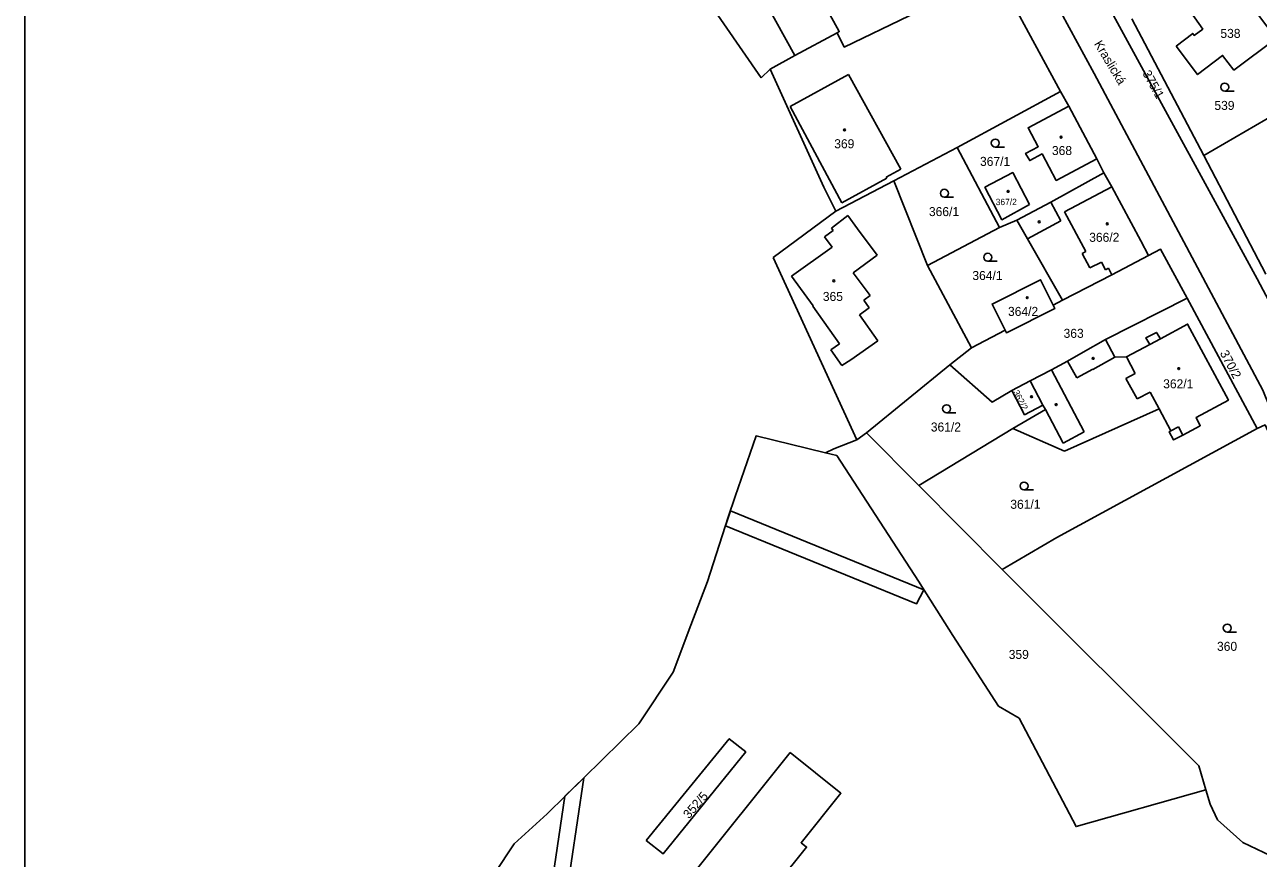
# Model space of a CAD drawing. Extents: x -869103 to -863415, y -1015889 to -1012477.
# Drawn here: x -867500 to -867267.3, y -1013218.1 to -1013060.8 of the extents above; entities that cross this region are included whole.
import ezdxf

# ---------------------------------------------------------------- set-up
doc = ezdxf.new("R2010")
doc.units = 0
for name, color, linetype in [('Hranice katastralního území', 7, 'Continuous'), ('Hranice parcel', 7, 'Continuous'), ('ML1000', 7, 'Continuous'), ('Parcelní čísla', 7, 'Continuous'), ('Pop  PČ popisy', 7, 'Continuous'), ('Vnitřní kresba', 7, 'Continuous'), ('Věcná břemena k části', 7, 'Continuous'), ('Značky budov', 7, 'Continuous'), ('Značky kultur', 7, 'Continuous')]:
    doc.layers.add(name, color=color, linetype=linetype)

msp = doc.modelspace()

# ---------------------------------------------------------------- linework, layer by layer
at = {"layer": 'Hranice katastralního území'}
for p, q in [((-867361.08, -1013070.83), (-867380.1, -1013043.27)), ((-867359.38, -1013069.2), (-867361.08, -1013070.83)), ((-867349.26, -1013091.48), (-867359.38, -1013069.2)), ((-867346.98, -1013096.01), (-867349.26, -1013091.48)), ((-867358.82, -1013104.69), (-867346.98, -1013096.01)), ((-867343.04, -1013139.1), (-867358.82, -1013104.69)), ((-867347.35, -1013140.84), (-867343.04, -1013139.1)), ((-867348.95, -1013141.56), (-867347.35, -1013140.84))]:
    msp.add_line(p, q, dxfattribs=at)
msp.add_lwpolyline([(-867412.61, -1013256.47), (-867414.85, -1013252.98), (-867416.96, -1013249.69), (-867421.06, -1013242.63), (-867420.77, -1013236.63), (-867419.53, -1013233.23), (-867415.2, -1013226.72), (-867407.64, -1013215.36), (-867401.46, -1013209.68), (-867384.12, -1013192.69), (-867377.65, -1013182.96), (-867374.36, -1013174.11), (-867371.17, -1013165.85), (-867367.29, -1013153.73), (-867365.95, -1013149.84), (-867362.01, -1013138.39), (-867348.95, -1013141.56)], dxfattribs=at)
at = {"layer": 'Hranice parcel'}
for p, q in [((-867361.08, -1013070.83), (-867380.1, -1013043.27)), ((-867304.61, -1013073.43), (-867315.9, -1013052.46)), ((-867298.26, -1013070), (-867307.69, -1013052.53)), ((-867291.15, -1013059.69), (-867277.56, -1013085.49)), ((-867354.69, -1013066.58), (-867346.74, -1013062.33)), ((-867354.69, -1013066.58), (-867359.38, -1013069.2)), ((-867359.38, -1013069.2), (-867361.08, -1013070.83)), ((-867349.26, -1013091.48), (-867359.38, -1013069.2)), ((-867304.61, -1013073.43), (-867324.1, -1013083.99)), ((-867303.02, -1013076.2), (-867304.61, -1013073.43)), ((-867297.75, -1013086.1), (-867303.02, -1013076.2)), ((-867277.56, -1013085.49), (-867261.75, -1013076.31)), ((-867324.1, -1013083.99), (-867336.02, -1013090.25)), ((-867316.12, -1013099.03), (-867324.1, -1013083.99)), ((-867296.4, -1013088.72), (-867297.75, -1013086.1)), ((-867277.56, -1013085.49), (-867265.83, -1013107.87)), ((-867346.98, -1013096.01), (-867349.26, -1013091.48)), ((-867336.02, -1013090.25), (-867346.98, -1013096.01)), ((-867336.02, -1013090.25), (-867329.69, -1013106.24)), ((-867358.82, -1013104.69), (-867346.98, -1013096.01)), ((-867312.83, -1013097.66), (-867316.12, -1013099.03)), ((-867316.12, -1013099.03), (-867329.69, -1013106.24)), ((-867343.04, -1013139.1), (-867358.82, -1013104.69)), ((-867329.69, -1013106.24), (-867321.39, -1013121.76)), ((-867260.77, -1013121.49), (-867267.49, -1013108.76)), ((-867296.12, -1013120.19), (-867280.67, -1013112.38)), ((-867267.48, -1013136.99), (-867280.67, -1013112.38)), ((-867304.19, -1013112.8), (-867306, -1013113.74)), ((-867315.03, -1013118.45), (-867321.39, -1013121.76)), ((-867321.39, -1013121.76), (-867325.46, -1013124.98)), ((-867325.46, -1013124.98), (-867341.22, -1013137.8)), ((-867313.78, -1013129.81), (-867310.31, -1013128.01)), ((-867310.31, -1013128.01), (-867307.91, -1013132.55)), ((-867341.22, -1013137.8), (-867343.04, -1013139.1)), ((-867331.35, -1013147.75), (-867341.22, -1013137.8)), ((-867313.57, -1013137), (-867331.35, -1013147.75)), ((-867303.82, -1013141.23), (-867313.57, -1013137)), ((-867347.35, -1013140.84), (-867343.04, -1013139.1)), ((-867348.95, -1013141.56), (-867347.35, -1013140.84)), ((-867315.6, -1013163.61), (-867331.35, -1013147.75))]:
    msp.add_line(p, q, dxfattribs=at)
for points in [[(-867267.49, -1013108.76), (-867293.45, -1013061.16), (-867304.41, -1013041.02)], [(-867346.74, -1013062.33), (-867346.32, -1013062.11), (-867353.77, -1013048.52), (-867362.18, -1013053.03), (-867354.69, -1013066.58)], [(-867315.9, -1013052.46), (-867320.88, -1013053.15), (-867345.39, -1013065.02), (-867346.74, -1013062.33)], [(-867282.8, -1013064.84), (-867278.72, -1013070.22), (-867274.01, -1013066.61), (-867271.88, -1013069.37), (-867263.9, -1013063.38), (-867272.32, -1013052.18), (-867276.15, -1013055.03), (-867276.98, -1013053.9), (-867281.08, -1013056.94), (-867277.77, -1013061.63), (-867279.35, -1013062.81), (-867279.64, -1013062.43), (-867282.8, -1013064.84)], [(-867264.14, -1013135.32), (-867266.41, -1013129.74), (-867298.26, -1013070)], [(-867297.75, -1013086.1), (-867305.39, -1013090.17), (-867308.06, -1013085.19), (-867310.38, -1013086.43), (-867311.19, -1013085.07), (-867308.79, -1013083.83), (-867310.71, -1013080.24), (-867303.02, -1013076.2)], [(-867310.42, -1013094.74), (-867315.64, -1013097.6), (-867318.86, -1013091.48), (-867313.59, -1013088.71), (-867310.42, -1013094.74)], [(-867296.4, -1013088.72), (-867306.4, -1013094.25), (-867312.83, -1013097.66)], [(-867287.99, -1013104.36), (-867289.46, -1013101.55), (-867294.9, -1013091.36), (-867296.4, -1013088.72)], [(-867304.19, -1013112.8), (-867310.8, -1013101.22), (-867312.83, -1013097.66)], [(-867287.99, -1013104.36), (-867294.9, -1013107.96), (-867304.19, -1013112.8)], [(-867280.67, -1013112.38), (-867285.73, -1013103.14), (-867287.99, -1013104.36)], [(-867315.03, -1013118.45), (-867317.51, -1013113.51), (-867308.35, -1013108.93), (-867306, -1013113.74)], [(-867306, -1013113.74), (-867305.69, -1013114.37), (-867314.79, -1013118.93), (-867315.03, -1013118.45)], [(-867296.12, -1013120.19), (-867294.35, -1013123.53), (-867292.17, -1013123.49), (-867287.75, -1013121.12), (-867288.52, -1013119.9), (-867286.51, -1013118.86), (-867285.74, -1013120.04), (-867280.61, -1013117.29), (-867272.92, -1013131.61), (-867279, -1013134.88), (-867278.22, -1013136.47), (-867281.53, -1013138.22), (-867283.26, -1013139.14), (-867284.09, -1013137.58), (-867283.78, -1013137.42), (-867286, -1013133.25), (-867303.82, -1013141.23)], [(-867310.31, -1013128.01), (-867306.27, -1013125.91), (-867303.27, -1013124.27), (-867300.34, -1013122.55), (-867300.31, -1013122.61), (-867296.12, -1013120.19)], [(-867325.46, -1013124.98), (-867317.46, -1013132), (-867313.78, -1013129.81)], [(-867307.91, -1013132.55), (-867311.36, -1013134.38), (-867313.78, -1013129.81)], [(-867313.57, -1013137), (-867307.45, -1013133.42), (-867307.91, -1013132.55)], [(-867267.48, -1013136.99), (-867305.28, -1013157.54), (-867315.6, -1013163.61)], [(-867243.12, -1013205.2), (-867247.84, -1013187.36), (-867252.77, -1013171.09), (-867262.16, -1013144.85), (-867265.99, -1013136.32), (-867267.48, -1013136.99)], [(-867412.61, -1013256.47), (-867414.85, -1013252.98), (-867416.96, -1013249.69), (-867421.06, -1013242.63), (-867420.77, -1013236.63), (-867419.53, -1013233.23), (-867415.2, -1013226.72), (-867407.64, -1013215.36), (-867401.46, -1013209.68), (-867384.12, -1013192.69), (-867377.65, -1013182.96), (-867374.36, -1013174.11), (-867371.17, -1013165.85), (-867367.29, -1013153.73), (-867365.95, -1013149.84), (-867362.01, -1013138.39), (-867348.95, -1013141.56)], [(-867277.16, -1013205.15), (-867301.64, -1013212.09), (-867312.39, -1013191.66), (-867316.32, -1013189.34), (-867324.93, -1013176.05), (-867331.38, -1013165.81), (-867346.81, -1013142.08), (-867348.95, -1013141.56)], [(-867277.16, -1013205.15), (-867278.5, -1013200.64), (-867315.6, -1013163.61)], [(-867382.75, -1013214.71), (-867379.58, -1013217.25), (-867363.97, -1013198.01), (-867367.07, -1013195.53), (-867382.75, -1013214.71)], [(-867355.61, -1013198.13), (-867393.2, -1013245.06), (-867383.58, -1013252.9), (-867376.4, -1013243.7), (-867375.39, -1013244.5), (-867352.51, -1013215.94), (-867353.52, -1013215.13), (-867346.03, -1013205.8), (-867355.61, -1013198.13)], [(-867240.42, -1013238.35), (-867259.2, -1013218.82), (-867259.19, -1013218.51), (-867264.89, -1013217.61), (-867270.21, -1013215.06), (-867274.99, -1013210.83), (-867276.39, -1013207.88), (-867277.16, -1013205.15)]]:
    msp.add_lwpolyline(points, dxfattribs=at)
at = {"layer": 'ML1000'}
msp.add_lwpolyline([(-867500, -1013000), (-866875, -1013000), (-866875, -1013500), (-867500, -1013500)], close=True, dxfattribs=at)
at = {"layer": 'Vnitřní kresba'}
for p, q in [((-867355.59, -1013076.25), (-867344.57, -1013070.17)), ((-867334.74, -1013088.05), (-867344.57, -1013070.17)), ((-867345.83, -1013094.4), (-867355.59, -1013076.25)), ((-867337.47, -1013089.54), (-867334.74, -1013088.05)), ((-867345.83, -1013094.4), (-867337.35, -1013089.78)), ((-867337.35, -1013089.78), (-867337.47, -1013089.54)), ((-867294.9, -1013091.36), (-867303.85, -1013096.09)), ((-867306.4, -1013094.25), (-867304.53, -1013097.79)), ((-867303.85, -1013096.09), (-867299.82, -1013103.61)), ((-867344.71, -1013096.82), (-867347.82, -1013099.16)), ((-867342.86, -1013099.3), (-867344.71, -1013096.82)), ((-867304.53, -1013097.79), (-867310.8, -1013101.22)), ((-867347.46, -1013099.64), (-867349.12, -1013100.85)), ((-867347.82, -1013099.16), (-867347.46, -1013099.64)), ((-867339.15, -1013104.3), (-867342.86, -1013099.3)), ((-867355.34, -1013108.25), (-867347.7, -1013102.77)), ((-867347.7, -1013102.77), (-867349.12, -1013100.85)), ((-867339.15, -1013104.3), (-867343.68, -1013107.59)), ((-867299.82, -1013103.61), (-867300.53, -1013103.98)), ((-867300.53, -1013103.98), (-867299.08, -1013106.69)), ((-867343.68, -1013107.59), (-867340.49, -1013111.9)), ((-867299.08, -1013106.69), (-867296.86, -1013105.6)), ((-867296.86, -1013105.6), (-867296.1, -1013107.02)), ((-867296.1, -1013107.02), (-867295.55, -1013106.73)), ((-867294.9, -1013107.96), (-867295.55, -1013106.73)), ((-867351.25, -1013113.86), (-867355.34, -1013108.25)), ((-867340.49, -1013111.9), (-867341.7, -1013112.76)), ((-867351.33, -1013113.92), (-867351.25, -1013113.86)), ((-867346.3, -1013121), (-867351.33, -1013113.92)), ((-867340.69, -1013114.2), (-867342.52, -1013115.56)), ((-867341.7, -1013112.76), (-867340.69, -1013114.2)), ((-867342.52, -1013115.56), (-867339.08, -1013120.43)), ((-867346.3, -1013121), (-867347.93, -1013122.16)), ((-867339.08, -1013120.43), (-867344.15, -1013124.02)), ((-867287.75, -1013121.12), (-867285.74, -1013120.04)), ((-867347.93, -1013122.16), (-867345.87, -1013125.08)), ((-867344.15, -1013124.02), (-867345.87, -1013125.08)), ((-867298.48, -1013125.86), (-867294.35, -1013123.53)), ((-867292.17, -1013123.49), (-867290.49, -1013126.62)), ((-867306.27, -1013125.91), (-867300.13, -1013137.61)), ((-867303.27, -1013124.27), (-867301.49, -1013127.45)), ((-867301.49, -1013127.45), (-867298.52, -1013125.79)), ((-867298.52, -1013125.79), (-867298.48, -1013125.86)), ((-867290.49, -1013126.62), (-867292.26, -1013127.52)), ((-867292.26, -1013127.52), (-867290.15, -1013131.41)), ((-867290.15, -1013131.41), (-867287.65, -1013130.14)), ((-867286, -1013133.25), (-867287.65, -1013130.14)), ((-867304.12, -1013139.74), (-867307.45, -1013133.42)), ((-867300.13, -1013137.61), (-867304.12, -1013139.74)), ((-867283.78, -1013137.42), (-867282.36, -1013136.66)), ((-867282.36, -1013136.66), (-867281.53, -1013138.22))]:
    msp.add_line(p, q, dxfattribs=at)
at = {"layer": 'Věcná břemena k části'}
for points in [[(-867366.87, -1013152.5), (-867367.81, -1013155.35), (-867331.78, -1013170.07), (-867330.38, -1013167.4)], [(-867405.16, -1013274.51), (-867404.1, -1013267.31), (-867394.54, -1013202.9), (-867398.09, -1013206.37), (-867406.62, -1013263.92), (-867408.24, -1013274.77), (-867396.53, -1013310.78), (-867392.99, -1013311.96)]]:
    msp.add_lwpolyline(points, close=True, dxfattribs=at)
at = {"layer": 'Značky budov'}
for centre in [(-867345.33, -1013080.66), (-867304.49, -1013082.01), (-867314.48, -1013092.25), (-867308.61, -1013097.99), (-867295.77, -1013098.36), (-867347.36, -1013109.11), (-867310.86, -1013112.3), (-867298.43, -1013123.75), (-867282.29, -1013125.69), (-867310.05, -1013130.98), (-867305.41, -1013132.48)]:
    msp.add_circle(centre, 0.175, dxfattribs=at)
at = {"layer": 'Značky kultur'}
for p, q in [((-867273.61, -1013073.33), (-867271.86, -1013073.33)), ((-867316.91, -1013083.89), (-867315.16, -1013083.89)), ((-867326.5, -1013093.36), (-867324.75, -1013093.36)), ((-867318.31, -1013105.42), (-867316.56, -1013105.42)), ((-867326.09, -1013134), (-867324.34, -1013134)), ((-867311.46, -1013148.58), (-867309.71, -1013148.58)), ((-867273.14, -1013175.38), (-867271.39, -1013175.38))]:
    msp.add_line(p, q, dxfattribs=at)
for centre in [(-867273.61, -1013072.58), (-867316.91, -1013083.14), (-867326.5, -1013092.61), (-867318.31, -1013104.67), (-867326.09, -1013133.25), (-867311.46, -1013147.83), (-867273.14, -1013174.63)]:
    msp.add_circle(centre, 0.75, dxfattribs=at)

# ---------------------------------------------------------------- texts
at = {"layer": 'Parcelní čísla'}
for s, height, p in [('538', 1.7, (-867274.43, -1013063.29)), ('539', 1.7, (-867275.56, -1013076.88)), ('369', 1.7, (-867347.28, -1013084.11)), ('368', 1.7, (-867306.21, -1013085.39)), ('367/1', 1.7, (-867319.78, -1013087.44)), ('367/2', 1.19, (-867316.82, -1013094.84)), ('366/1', 1.7, (-867329.41, -1013096.91)), ('366/2', 1.7, (-867299.18, -1013101.76)), ('364/1', 1.7, (-867321.22, -1013108.97)), ('365', 1.7, (-867349.43, -1013112.92)), ('364/2', 1.7, (-867314.5, -1013115.74)), ('363', 1.7, (-867304.01, -1013119.88)), ('362/1', 1.7, (-867285.22, -1013129.4)), ('361/2', 1.7, (-867329.06, -1013137.55)), ('361/1', 1.7, (-867314.06, -1013152.13)), ('360', 1.7, (-867275.07, -1013178.93)), ('359', 1.7, (-867314.36, -1013180.46))]:
    msp.add_text(s, height=height, dxfattribs=at).set_placement(p)
for s, height, rotation, p in [('375/1', 1.7, 299, (-867289.19, -1013069.97)), ('370/2', 1.7, 298, (-867274.58, -1013122.75)), ('362/2', 1.19, 298, (-867313.57, -1013130.15)), ('352/5', 1.7, 49, (-867374.68, -1013210.73))]:
    msp.add_text(s, height=height, rotation=rotation, dxfattribs=at).set_placement(p)
at = {"layer": 'Pop  PČ popisy'}
msp.add_text('Kraslická', height=1.7, rotation=301, dxfattribs=at).set_placement((-867298.33, -1013064.41))

doc.saveas('drawing.dxf')
